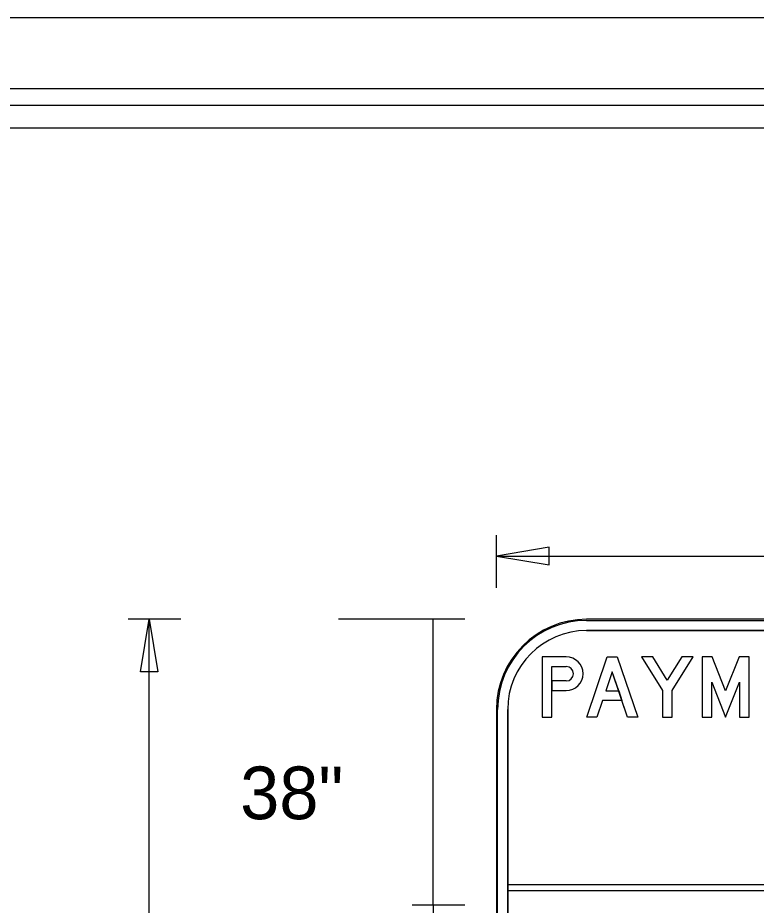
# Model space of a CAD drawing. Extents: x 17890628 to 17891459, y 17897314 to 17897992.
# Drawn here: x 17890794.41 to 17890802.6, y 17897486.98 to 17897496.82 of the extents above; entities that cross this region are included whole.
import ezdxf

# ---------------------------------------------------------------- set-up
doc = ezdxf.new("R2010")
doc.units = 0
for name, color, linetype in [('GSColorFill', 7, 'Continuous'), ('GSDims', 7, 'Continuous'), ('GSOutline', 7, 'Continuous'), ('PlotBorder_dp', 7, 'Continuous'), ('SheetBorder_dp', 7, 'Continuous'), ('SheetLinesMisc2_dp', 7, 'Continuous'), ('XSCell', 7, 'Continuous')]:
    doc.layers.add(name, color=color, linetype=linetype)

msp = doc.modelspace()

# ---------------------------------------------------------------- linework, layer by layer
at = {"layer": 'GSColorFill'}
for p, q in [((17890809.2156, 17897490.1529), (17890800.7156, 17897490.1529)), ((17890809.2156, 17897490.1529), (17890800.7156, 17897490.1529)), ((17890809.2156, 17897490.1529), (17890800.7156, 17897490.1529)), ((17890800.7156, 17897490.1404), (17890809.2156, 17897490.1404)), ((17890800.7156, 17897490.0279), (17890809.2156, 17897490.0279)), ((17890800.3293, 17897489.6296), (17890800.4893, 17897489.6296)), ((17890799.7156, 17897489.1529), (17890799.7156, 17897482.1529)), ((17890799.7156, 17897489.1529), (17890799.7156, 17897482.1529)), ((17890799.7156, 17897489.1529), (17890799.7156, 17897482.1529)), ((17890799.7281, 17897482.1529), (17890799.7281, 17897489.1529)), ((17890799.8406, 17897482.1529), (17890799.8406, 17897489.1529)), ((17890810.0908, 17897487.2089), (17890799.8408, 17897487.2089)), ((17890799.8408, 17897487.2089), (17890799.8408, 17897487.1464)), ((17890799.8408, 17897487.1464), (17890810.0908, 17897487.1464))]:
    msp.add_line(p, q, dxfattribs=at)
for points in [[(17890800.4893, 17897489.7362), (17890800.2226, 17897489.7362), (17890800.2226, 17897489.0696), (17890800.3293, 17897489.0696), (17890800.3293, 17897489.6296)], [(17890800.4893, 17897489.4696), (17890800.3293, 17897489.4696), (17890800.3293, 17897489.3629), (17890800.4893, 17897489.3629)]]:
    msp.add_lwpolyline(points, dxfattribs=at)
for points in [[(17890800.716, 17897489.0696), (17890800.9426, 17897489.7362), (17890801.0559, 17897489.7362), (17890801.2826, 17897489.0696), (17890801.17, 17897489.0696), (17890800.9993, 17897489.5715), (17890800.9272, 17897489.3595), (17890801.0713, 17897489.3595), (17890801.1076, 17897489.2528), (17890800.8909, 17897489.2528), (17890800.8286, 17897489.0696)], [(17890801.5559, 17897489.0696), (17890801.6626, 17897489.0696), (17890801.6626, 17897489.3629), (17890801.8959, 17897489.7362), (17890801.7702, 17897489.7362), (17890801.6093, 17897489.4788), (17890801.4484, 17897489.7362), (17890801.3226, 17897489.7362), (17890801.5559, 17897489.3629)], [(17890802.5159, 17897489.0696), (17890802.5159, 17897489.7362), (17890802.4056, 17897489.7362), (17890802.2559, 17897489.3589), (17890802.1063, 17897489.7362), (17890801.996, 17897489.7362), (17890801.996, 17897489.0696), (17890802.1026, 17897489.0696), (17890802.1026, 17897489.4562), (17890802.2559, 17897489.0696), (17890802.4093, 17897489.4562), (17890802.4093, 17897489.0696)]]:
    msp.add_lwpolyline(points, close=True, dxfattribs=at)
for radius in [1, 1, 1, 0.9875, 0.875]:
    msp.add_arc((17890800.7156, 17897489.1529), radius, 90, 180, dxfattribs=at)
for major_axis in [(0, 0.1867), (0, 0.08)]:
    msp.add_ellipse((17890800.4893, 17897489.5496), major_axis=major_axis, ratio=0.999994, start_param=3.141593, end_param=6.283185, dxfattribs=at)
at = {"layer": 'GSDims'}
for p, q in [((17890799.7156, 17897490.5029), (17890799.7156, 17897491.0862)), ((17890799.7156, 17897490.5029), (17890799.7156, 17897491.0862)), ((17890799.7156, 17897490.5029), (17890799.7156, 17897491.0862)), ((17890799.7156, 17897490.5029), (17890799.7156, 17897491.0862)), ((17890799.7156, 17897490.5029), (17890799.7156, 17897491.0862)), ((17890799.7156, 17897490.8529), (17890810.2156, 17897490.8529)), ((17890799.7156, 17897490.5029), (17890799.7156, 17897490.5029)), ((17890799.7156, 17897490.5029), (17890799.7156, 17897490.5029)), ((17890799.7156, 17897490.5029), (17890799.7156, 17897490.5029)), ((17890799.7156, 17897490.5029), (17890799.7156, 17897490.5029)), ((17890799.7156, 17897490.5029), (17890799.7156, 17897490.5029)), ((17890796.2156, 17897490.1529), (17890795.6323, 17897490.1529)), ((17890796.2156, 17897490.1529), (17890795.6323, 17897490.1529)), ((17890796.2156, 17897490.1529), (17890795.6323, 17897490.1529)), ((17890796.2156, 17897490.1529), (17890795.6323, 17897490.1529)), ((17890796.2156, 17897490.1529), (17890795.6323, 17897490.1529)), ((17890795.8656, 17897481.1529), (17890795.8656, 17897490.1529)), ((17890799.3656, 17897490.1529), (17890797.9656, 17897490.1529)), ((17890799.3656, 17897490.1529), (17890797.9656, 17897490.1529)), ((17890799.3656, 17897490.1529), (17890797.9656, 17897490.1529)), ((17890799.3656, 17897490.1529), (17890797.9656, 17897490.1529)), ((17890799.3656, 17897490.1529), (17890797.9656, 17897490.1529)), ((17890799.3656, 17897490.1529), (17890798.7823, 17897490.1529)), ((17890799.3656, 17897490.1529), (17890798.7823, 17897490.1529)), ((17890799.3656, 17897490.1529), (17890798.7823, 17897490.1529)), ((17890799.3656, 17897490.1529), (17890798.7823, 17897490.1529)), ((17890799.3656, 17897490.1529), (17890798.7823, 17897490.1529)), ((17890799.0156, 17897486.984), (17890799.0156, 17897490.1529)), ((17890799.3656, 17897486.984), (17890798.7823, 17897486.984)), ((17890799.0156, 17897486.984), (17890799.0156, 17897485.484))]:
    msp.add_line(p, q, dxfattribs=at)
for points in [[(17890799.7156, 17897490.8529), (17890800.2989, 17897490.7557), (17890800.2989, 17897490.9501)], [(17890795.8656, 17897490.1529), (17890795.9628, 17897489.5696), (17890795.7684, 17897489.5696)]]:
    msp.add_lwpolyline(points, close=True, dxfattribs=at)
at = {"layer": 'GSOutline'}
for p, q in [((17890809.2156, 17897490.1529), (17890800.7156, 17897490.1529)), ((17890800.7156, 17897490.0279), (17890809.2156, 17897490.0279)), ((17890800.3293, 17897489.6296), (17890800.4893, 17897489.6296)), ((17890799.7156, 17897489.1529), (17890799.7156, 17897482.1529)), ((17890799.8406, 17897482.1529), (17890799.8406, 17897489.1529)), ((17890810.0908, 17897487.2089), (17890799.8408, 17897487.2089)), ((17890799.8408, 17897487.2089), (17890799.8408, 17897487.1464)), ((17890799.8408, 17897487.1464), (17890810.0908, 17897487.1464))]:
    msp.add_line(p, q, dxfattribs=at)
for points in [[(17890800.4893, 17897489.7362), (17890800.2226, 17897489.7362), (17890800.2226, 17897489.0696), (17890800.3293, 17897489.0696), (17890800.3293, 17897489.6296)], [(17890800.4893, 17897489.4696), (17890800.3293, 17897489.4696), (17890800.3293, 17897489.3629), (17890800.4893, 17897489.3629)]]:
    msp.add_lwpolyline(points, dxfattribs=at)
for points in [[(17890800.716, 17897489.0696), (17890800.9426, 17897489.7362), (17890801.0559, 17897489.7362), (17890801.2826, 17897489.0696), (17890801.17, 17897489.0696), (17890800.9993, 17897489.5715), (17890800.9272, 17897489.3595), (17890801.0713, 17897489.3595), (17890801.1076, 17897489.2528), (17890800.8909, 17897489.2528), (17890800.8286, 17897489.0696)], [(17890801.5559, 17897489.0696), (17890801.6626, 17897489.0696), (17890801.6626, 17897489.3629), (17890801.8959, 17897489.7362), (17890801.7702, 17897489.7362), (17890801.6093, 17897489.4788), (17890801.4484, 17897489.7362), (17890801.3226, 17897489.7362), (17890801.5559, 17897489.3629)], [(17890802.5159, 17897489.0696), (17890802.5159, 17897489.7362), (17890802.4056, 17897489.7362), (17890802.2559, 17897489.3589), (17890802.1063, 17897489.7362), (17890801.996, 17897489.7362), (17890801.996, 17897489.0696), (17890802.1026, 17897489.0696), (17890802.1026, 17897489.4562), (17890802.2559, 17897489.0696), (17890802.4093, 17897489.4562), (17890802.4093, 17897489.0696)]]:
    msp.add_lwpolyline(points, close=True, dxfattribs=at)
for radius in [1, 0.875]:
    msp.add_arc((17890800.7156, 17897489.1529), radius, 90, 180, dxfattribs=at)
for major_axis in [(0, 0.1867), (0, 0.08)]:
    msp.add_ellipse((17890800.4893, 17897489.5496), major_axis=major_axis, ratio=0.999994, start_param=3.141593, end_param=6.283185, dxfattribs=at)
at = {"layer": 'PlotBorder_dp'}
msp.add_lwpolyline([(17890701.3459, 17897413.6874), (17890830.7452, 17897413.6874), (17890830.7452, 17897496.8183), (17890701.3459, 17897496.8183)], close=True, dxfattribs=at)
at = {"layer": 'SheetBorder_dp'}
msp.add_line((17890705.6592, 17897496.034), (17890826.4319, 17897496.034), dxfattribs=at)
at = {"layer": 'SheetLinesMisc2_dp'}
for p, q in [((17890705.8722, 17897495.8488), (17890826.2225, 17897495.8488)), ((17890784.7149, 17897495.5993), (17890825.6472, 17897495.5993))]:
    msp.add_line(p, q, dxfattribs=at)
at = {"layer": 'XSCell'}
for p, q in [((17890809.2156, 17897490.1529), (17890800.7156, 17897490.1529)), ((17890809.2156, 17897490.0279), (17890800.7156, 17897490.0279)), ((17890800.3293, 17897489.3629), (17890800.4893, 17897489.3629)), ((17890799.7156, 17897489.1529), (17890799.7156, 17897482.1529)), ((17890799.8406, 17897489.1529), (17890799.8406, 17897482.1529)), ((17890810.0908, 17897487.2089), (17890799.8408, 17897487.2089)), ((17890799.8408, 17897487.2089), (17890799.8408, 17897487.1464)), ((17890799.8408, 17897487.1464), (17890810.0908, 17897487.1464))]:
    msp.add_line(p, q, dxfattribs=at)
for points in [[(17890800.4893, 17897489.7362), (17890800.2226, 17897489.7362), (17890800.2226, 17897489.0696), (17890800.3293, 17897489.0696), (17890800.3293, 17897489.3629)], [(17890800.4893, 17897489.4696), (17890800.3293, 17897489.4696), (17890800.3293, 17897489.6296), (17890800.4893, 17897489.6296)]]:
    msp.add_lwpolyline(points, dxfattribs=at)
for points in [[(17890800.8909, 17897489.2528), (17890800.8286, 17897489.0696), (17890800.716, 17897489.0696), (17890800.9426, 17897489.7362), (17890801.0559, 17897489.7362), (17890801.2826, 17897489.0696), (17890801.17, 17897489.0696), (17890801.1076, 17897489.2528)], [(17890801.5559, 17897489.0696), (17890801.6626, 17897489.0696), (17890801.6626, 17897489.3629), (17890801.8959, 17897489.7362), (17890801.7702, 17897489.7362), (17890801.6093, 17897489.4788), (17890801.4484, 17897489.7362), (17890801.3226, 17897489.7362), (17890801.5559, 17897489.3629)], [(17890802.5159, 17897489.0696), (17890802.5159, 17897489.7362), (17890802.4056, 17897489.7362), (17890802.2559, 17897489.3589), (17890802.1063, 17897489.7362), (17890801.996, 17897489.7362), (17890801.996, 17897489.0696), (17890802.1026, 17897489.0696), (17890802.1026, 17897489.4562), (17890802.2559, 17897489.0696), (17890802.4093, 17897489.4562), (17890802.4093, 17897489.0696)], [(17890800.9272, 17897489.3595), (17890801.0714, 17897489.3595), (17890800.9993, 17897489.5715)]]:
    msp.add_lwpolyline(points, close=True, dxfattribs=at)
for radius in [1, 0.875]:
    msp.add_arc((17890800.7156, 17897489.1529), radius, 90, 180, dxfattribs=at)
for major_axis in [(0, 0.1867), (0, 0.08)]:
    msp.add_ellipse((17890800.4893, 17897489.5496), major_axis=major_axis, ratio=0.999994, start_param=3.141593, end_param=6.283185, dxfattribs=at)

# ---------------------------------------------------------------- texts
at = {"layer": 'GSDims'}
msp.add_text('38"', height=0.58333, dxfattribs=at).set_placement((17890796.875, 17897487.9376))

doc.saveas('drawing.dxf')
